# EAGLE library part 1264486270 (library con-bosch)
BOSCH - Steckerleiste fahrzeugorientiert - 154 pol. Source: DRW_1264486270_000_03_1.pdf
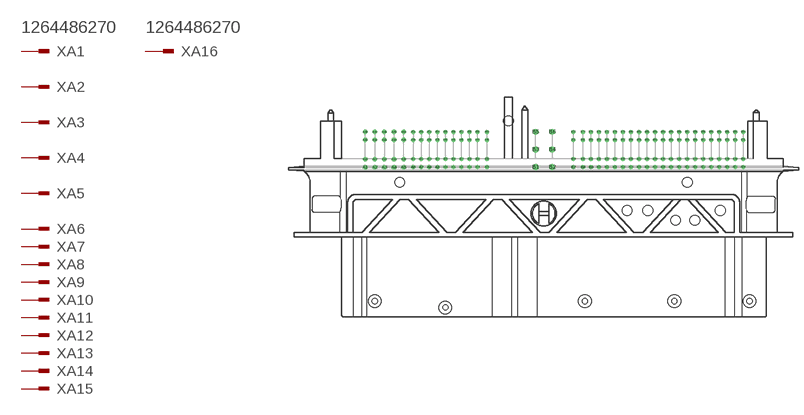
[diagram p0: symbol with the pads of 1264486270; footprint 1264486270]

Designator prefix X; gates A1=PIN-V A2=PIN A3=PIN A4=PIN A5=PIN A6=PIN A7=PIN A8=PIN A9=PIN A10=PIN A11=PIN A12=PIN A13=PIN A14=PIN A15=PIN A16=PIN-V A17=PIN A18=PIN A19=PIN A20=PIN A21=PIN A22=PIN A23=PIN A24=PIN A25=PIN A26=PIN A27=PIN A28=PIN A29=PIN A30=PIN A31=PIN-V A32=PIN A33=PIN A34=PIN A35=PIN A36=PIN A37=PIN A38=PIN A39=PIN A40=PIN A41=PIN A42=PIN A43=PIN A44=PIN A45=PIN A46=PIN-V A47=PIN A48=PIN A49=PIN A50=PIN A51=PIN A52=PIN A53=PIN A54=PIN A55=PIN A56=PIN A57=PIN A58=PIN A59=PIN A60=PIN B1=PIN-V B2=PIN B3=PIN B4=PIN B5=PIN B6=PIN B7=PIN B8=PIN B9=PIN B10=PIN B11=PIN B12=PIN B13=PIN B14=PIN B15=PIN B16=PIN B17=PIN B18=PIN B19=PIN B20=PIN B21=PIN B22=PIN B23=PIN B24=PIN B25=PIN B26=PIN B27=PIN B28=PIN B29=PIN B30=PIN B31=PIN B32=PIN B33=PIN B34=PIN B35=PIN B36=PIN B37=PIN B38=PIN B39=PIN B40=PIN B41=PIN B42=PIN B43=PIN B44=PIN B45=PIN B46=PIN B47=PIN B48=PIN B49=PIN B50=PIN B51=PIN B52=PIN B53=PIN B54=PIN B55=PIN B56=PIN B57=PIN B58=PIN B59=PIN B60=PIN B61=PIN B62=PIN B63=PIN B64=PIN B65=PIN B66=PIN B67=PIN B68=PIN B69=PIN B70=PIN B71=PIN B72=PIN B73=PIN B74=PIN B75=PIN B76=PIN B77=PIN B78=PIN B79=PIN B80=PIN B81=PIN B82=PIN B83=PIN B84=PIN B85=PIN B86=PIN B87=PIN B88=PIN B89=PIN B90=PIN B91=PIN B92=PIN B93=PIN B94=PIN

## 1264486270 (OC_FARNELL: unknown; OC_NEWARK: unknown)  [1264486270]
A1  A1:1  pas
A2  A2:1  pas
A3  A3:1  pas
A4  A4:1  pas
A5  A5:1  pas
A6  A6:1  pas
A7  A7:1  pas
A8  A8:1  pas
A9  A9:1  pas
A10  A10:1  pas
A11  A11:1  pas
A12  A12:1  pas
A13  A13:1  pas
A14  A14:1  pas
A15  A15:1  pas
A16  A16:1  pas
A17  A17:1  pas
A18  A18:1  pas
A19  A19:1  pas
A20  A20:1  pas
A21  A21:1  pas
A22  A22:1  pas
A23  A23:1  pas
A24  A24:1  pas
A25  A25:1  pas
A26  A26:1  pas
A27  A27:1  pas
A28  A28:1  pas
A29  A29:1  pas
A30  A30:1  pas
A31  A31:1  pas
A32  A32:1  pas
A33  A33:1  pas
A34  A34:1  pas
A35  A35:1  pas
A36  A36:1  pas
A37  A37:1  pas
A38  A38:1  pas
A39  A39:1  pas
A40  A40:1  pas
A41  A41:1  pas
A42  A42:1  pas
A43  A43:1  pas
A44  A44:1  pas
A45  A45:1  pas
A46  A46:1  pas
A47  A47:1  pas
A48  A48:1  pas
A49  A49:1  pas
A50  A50:1  pas
A51  A51:1  pas
A52  A52:1  pas
A53  A53:1  pas
A54  A54:1  pas
A55  A55:1  pas
A56  A56:1  pas
A57  A57:1  pas
A58  A58:1  pas
A59  A59:1  pas
A60  A60:1  pas
B1  B1:1  pas
B2  B2:1  pas
B3  B3:1  pas
B4  B4:1  pas
B5  B5:1  pas
B6  B6:1  pas
B7  B7:1  pas
B8  B8:1  pas
B9  B9:1  pas
B10  B10:1  pas
B11  B11:1  pas
B12  B12:1  pas
B13  B13:1  pas
B14  B14:1  pas
B15  B15:1  pas
B16  B16:1  pas
B17  B17:1  pas
B18  B18:1  pas
B19  B19:1  pas
B20  B20:1  pas
B21  B21:1  pas
B22  B22:1  pas
B23  B23:1  pas
B24  B24:1  pas
B25  B25:1  pas
B26  B26:1  pas
B27  B27:1  pas
B28  B28:1  pas
B29  B29:1  pas
B30  B30:1  pas
B31  B31:1  pas
B32  B32:1  pas
B33  B33:1  pas
B34  B34:1  pas
B35  B35:1  pas
B36  B36:1  pas
B37  B37:1  pas
B38  B38:1  pas
B39  B39:1  pas
B40  B40:1  pas
B41  B41:1  pas
B42  B42:1  pas
B43  B43:1  pas
B44  B44:1  pas
B45  B45:1  pas
B46  B46:1  pas
B47  B47:1  pas
B48  B48:1  pas
B49  B49:1  pas
B50  B50:1  pas
B51  B51:1  pas
B52  B52:1  pas
B53  B53:1  pas
B54  B54:1  pas
B55  B55:1  pas
B56  B56:1  pas
B57  B57:1  pas
B58  B58:1  pas
B59  B59:1  pas
B60  B60:1  pas
B61  B61:1  pas
B62  B62:1  pas
B63  B63:1  pas
B64  B64:1  pas
B65  B65:1  pas
B66  B66:1  pas
B67  B67:1  pas
B68  B68:1  pas
B69  B69:1  pas
B70  B70:1  pas
B71  B71:1  pas
B72  B72:1  pas
B73  B73:1  pas
B74  B74:1  pas
B75  B75:1  pas
B76  B76:1  pas
B77  B77:1  pas
B78  B78:1  pas
B79  B79:1  pas
B80  B80:1  pas
B81  B81:1  pas
B82  B82:1  pas
B83  B83:1  pas
B84  B84:1  pas
B85  B85:1  pas
B86  B86:1  pas
B87  B87:1  pas
B88  B88:1  pas
B89  B89:1  pas
B90  B90:1  pas
B91  B91:1  pas
B92  B92:1  pas
B93  B93:1  pas
B94  B94:1  pas

## Footprint 1264486270 (pad centres in mm)
BOSCH - Steckerleiste fahrzeugorientiert - 154 pol. Source: DRW_1264486270_000_03_1.pdf
drill 0.8 pad 1.422 round: A1 -55.747,5.45; A2 -52.747,5.45; A3 -49.747,5.45; A4 -46.747,5.45; A5 -43.747,5.45; A16 -55.747,7.95; A17 -52.747,7.95; A18 -49.747,7.95; A19 -46.747,7.95; A20 -43.747,7.95; A31 -55.747,13.95; A32 -52.747,13.95; A33 -49.747,13.95; A34 -46.747,13.95; A35 -43.747,13.95; A46 -55.747,16.45; A47 -52.747,16.45; A48 -49.747,16.45; A49 -46.747,16.45; A50 -43.747,16.45
drill 0.7 pad 1.27 round: A6 -40.747,5.45; A7 -38.247,5.45; A8 -35.747,5.45; A9 -33.247,5.45; A10 -30.747,5.45; A11 -28.247,5.45; A12 -25.747,5.45; A13 -23.247,5.45; A14 -20.747,5.45; A15 -17.747,5.45; A21 -40.747,7.95; A22 -38.247,7.95; A23 -35.747,7.95; A24 -33.247,7.95; A25 -30.747,7.95; A26 -28.247,7.95; A27 -25.747,7.95; A28 -23.247,7.95; A29 -20.747,7.95; A30 -17.747,7.95; A36 -40.747,13.95; A37 -38.247,13.95; A38 -35.747,13.95; A39 -33.247,13.95; A40 -30.747,13.95; A41 -28.247,13.95; A42 -25.747,13.95; A43 -23.247,13.95; A44 -20.747,13.95; A45 -17.747,13.95; A51 -40.747,16.45; A52 -38.247,16.45; A53 -35.747,16.45; A54 -33.247,16.45; A55 -30.747,16.45; A56 -28.247,16.45; A57 -25.747,16.45; A58 -23.247,16.45; A59 -20.747,16.45; A60 -17.747,16.45; B7 9.253,5.45; B8 12.253,5.45; B9 14.753,5.45; B10 17.253,5.45; B11 19.753,5.45; B12 22.253,5.45; B13 24.753,5.45; B14 27.253,5.45; B15 29.753,5.45; B16 32.253,5.45; B17 34.753,5.45; B18 37.253,5.45; B19 39.753,5.45; B20 42.253,5.45; B21 44.753,5.45; B22 47.253,5.45; B23 49.753,5.45; B24 52.253,5.45; B25 54.753,5.45; B26 57.253,5.45; B27 59.753,5.45; B28 62.253,5.45; B29 9.253,7.95; B30 12.253,7.95; B31 14.753,7.95; B32 17.253,7.95; B33 19.753,7.95; B34 22.253,7.95; B35 24.753,7.95; B36 27.253,7.95; B37 29.753,7.95; B38 32.253,7.95; B39 34.753,7.95; B40 37.253,7.95; B41 39.753,7.95; B42 42.253,7.95; B43 44.753,7.95; B44 47.253,7.95; B45 49.753,7.95; B46 52.253,7.95; B47 54.753,7.95; B48 57.253,7.95; B49 59.753,7.95; B50 62.253,7.95; B51 9.253,13.95; B52 12.253,13.95; B53 14.753,13.95; B54 17.253,13.95; B55 19.753,13.95; B56 22.253,13.95; B57 24.753,13.95; B58 27.253,13.95; B59 29.753,13.95; B60 32.253,13.95; B61 34.753,13.95; B62 37.253,13.95; B63 39.753,13.95; B64 42.253,13.95; B65 44.753,13.95; B66 47.253,13.95; B67 49.753,13.95; B68 52.253,13.95; B69 54.753,13.95; B70 57.253,13.95; B71 59.753,13.95; B72 62.253,13.95; B73 9.253,16.45; B74 12.253,16.45; B75 14.753,16.45; B76 17.253,16.45; B77 19.753,16.45; B78 22.253,16.45; B79 24.753,16.45; B80 27.253,16.45; B81 29.753,16.45; B82 32.253,16.45; B83 34.753,16.45; B84 37.253,16.45; B85 39.753,16.45; B86 42.253,16.45; B87 44.753,16.45; B88 47.253,16.45; B89 49.753,16.45; B90 52.253,16.45; B91 54.753,16.45; B92 57.253,16.45; B93 59.753,16.45; B94 62.253,16.45
drill 0.8 pad 1.778 round: B1 -2.547,5.45; B2 2.653,5.45; B3 -2.547,10.95; B4 2.653,10.95; B5 -2.547,16.45; B6 2.653,16.45
hole 3 at -44.991,0.767
hole 3 at 44.826,0.767
hole 3 at -11.015,19.892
